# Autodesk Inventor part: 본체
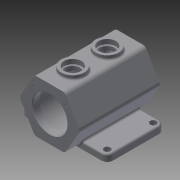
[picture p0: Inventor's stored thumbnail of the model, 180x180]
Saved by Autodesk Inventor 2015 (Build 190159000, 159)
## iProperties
Created: 2021-06
Part Number: 본체
Material: 일반
Document SubType Name: Modeling
Designer: now
Density: 1 g/cm^3
Appearance: 기본값
Author: now
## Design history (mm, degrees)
sketch "스케치6" dims "d57" = 105
  geometry: L1 (-52.5, 0)-(-26.25, 45.466); L2 (-26.25, 45.466)-(26.25, 45.466); L3 (26.25, 45.466)-(52.5, 0); L4 (52.5, 0)-(26.25, -45.466); L5 (26.25, -45.466)-(-26.25, -45.466); L6 (-26.25, -45.466)-(-52.5, 0); 3 further points
  constraints: 12 end point, 2 coincident, 1 horizontal, 1 horizontal alignment, 15 other
extrude "돌출3" new body sketch "스케치6" stored distance "d20" = 140; taper "d21" = 0 deg
node "작업 평면7"
sketch "스케치11"
  geometry: L1 (-75, -45)-(75, -45); L2 (75, -45)-(75, 55); L3 (75, 55)-(-75, 55); L4 (-75, 55)-(-75, -45); L5 (-26.25, -70)-(26.25, -70) reference; 3 further points
  constraints: 8 end point, 2 midpoint, 2 parallel, 1 horizontal, 1 perpendicular, 1 vertical alignment
  dimensions: "d41" = 100 distance of L3.end L1.start; "d42" = 150 distance of L2.end L3.end; "d43" = 25 distance between parallel lines of L1 L5
extrude "돌출5" join sketch "스케치11" distance "d44" = 12; taper "d45" = 0 deg
node "작업 평면8"
sketch "스케치13"
  geometry: L1 (26.25, -70)-(-26.25, -70) reference; C1 r 20 at (0, -30); C2 r 20 at (0, 30); 1 further point
  constraints: 2 centre point
  dimensions: "d48" = 20 radius of C1; "d49" = 20 radius of C2; "d52" = 40 distance from line of C1.centre L1; "d53" = 60 distance of C2.centre C1.centre
extrude "돌출6" join sketch "스케치13" stored distance "d54" = 12; taper "d55" = 0 deg
sketch "스케치14"
  geometry: C1 r 30 at (0, 0); 1 further point
  constraints: 1 centre point, 1 coincident
  dimensions: "d56" = 30 radius of C1
extrude "돌출7" cut sketch "스케치14" distance "d58" = 12; taper "d59" = 0 deg
sketch "스케치15"
  geometry: C1 r 30 at (0, 0) reference; C2 r 37.5 at (0, 0)
  constraints: 1 centre point, 1 coincident
  dimensions: "d60" = 37.5 radius of C2
extrude "돌출8" cut sketch "스케치15" distance "d61" = 116; taper "d62" = 0 deg
sketch "스케치16"
  geometry: C1 r 30 at (0, 0); 1 further point
  constraints: 1 centre point, 1 coincident
  dimensions: "d63" = 30 radius of C1
extrude "돌출9" cut sketch "스케치16" distance "d64" = 12; taper "d65" = 0 deg
fillet "모깎기1" dims "d66" = 10
hole "구멍1" diameter "d69" = 11; stored, may be unused: countersink angle "d73" = 90 deg, drill point angle "d75" = 118 deg; dims "d67" = 10, "d68" = 10, "d70" = 6, "d71" = 4, "d72" = 2, "d74" = 8
hole "구멍2" diameter "d78" = 11; stored, may be unused: countersink angle "d82" = 90 deg, drill point angle "d84" = 118 deg; dims "d76" = 10, "d77" = 10, "d79" = 6, "d80" = 4, "d81" = 2, "d83" = 8
hole "구멍3" diameter "d87" = 11; stored, may be unused: countersink angle "d91" = 90 deg, drill point angle "d93" = 118 deg; dims "d85" = 10, "d86" = 10, "d88" = 6, "d89" = 4, "d90" = 2, "d92" = 8
hole "구멍4" diameter "d96" = 11; stored, may be unused: countersink angle "d100" = 90 deg, drill point angle "d102" = 118 deg; dims "d94" = 10, "d95" = 10, "d97" = 6, "d98" = 4, "d99" = 2, "d101" = 8
hole "구멍5" diameter "d106" = 25; stored, may be unused: countersink angle "d110" = 90 deg, drill point angle "d112" = 118 deg; dims "d104" = 10, "d105" = 10, "d107" = 6, "d108" = 30, "d109" = 8, "d111" = 20
hole "구멍6" diameter "d115" = 25; stored, may be unused: countersink angle "d119" = 90 deg, drill point angle "d121" = 118 deg; dims "d113" = 10, "d114" = 10, "d116" = 6, "d117" = 30, "d118" = 8, "d120" = 20
fillet "모깎기2" dims "d133" = 8
fillet "모깎기4" dims "d135" = 8
fillet "모깎기5" dims "d136" = 3
fillet "모깎기6" dims "d137" = 3
fillet "모깎기7" dims "d138" = 3
chamfer "모따기1" distance "d139" = 1; stored, may be unused: second distance "d140" = 2, angle "d141" = 45 deg
sketch "스케치19"
  geometry: L1 (-75, 45)-(-75, -35) reference; L2 (-44.417, 55)-(-65, 55) reference; L3 (-65, -45)-(-44.417, -45) reference; 2 further points
  constraints: 1 other
  dimensions: "d142" = 14 distance from line of point (-61, 5) L1; "d176" = 50 distance from line of point (-61, 5) L3
feature "엠보싱1" sketch "스케치19" dims "d57" = 105, "d58" = 12, "d144" = 0.5, "d145" = 0, "d169" = 8
fillet "모깎기8" dims "d146" = 3
chamfer "모따기2" distance "d147" = 1; stored, may be unused: second distance "d148" = 2, angle "d149" = 45 deg
sketch "스케치21" dims "d152" = 40
  geometry: L1 (0, 0)-(-28.284, 28.284); L2 (0, 0)-(0, 25); C1 r 31 at (0, 0) reference; 1 further point
  constraints: 4 end point, 2 coincident, 1 vertical, 3 other
  dimensions: "d153" = 45 deg angle of L2 L1
hole "구멍8" sketch "스케치21" at (-28.284, 28.284) diameter "d154" = 3.242; stored, may be unused: countersink angle "d158" = 90 deg, drill point angle "d160" = 118 deg; dims "d155" = 8, "d156" = 30, "d157" = 8, "d159" = 10
fillet "모깎기9" dims "d164" = 5
sketch "스케치22" dims "d165" = 40
  geometry: C1 r 31 at (0, 0) reference; 2 further points
  constraints: 1 coincident, 1 vertical alignment, 2 other
hole "구멍9" sketch "스케치22" at (0, -40) diameter "d166" = 3.242; stored, may be unused: countersink angle "d170" = 90 deg, drill point angle "d172" = 118 deg; dims "d167" = 8, "d168" = 30, "d169" = 8, "d171" = 10
node "솔리드2"
pattern_circular "원형 패턴2" dims angle "d162" = 360 deg
pattern_circular "원형 패턴3" dims angle "d174" = 360 deg
other parameters: "d47" = 52.5
